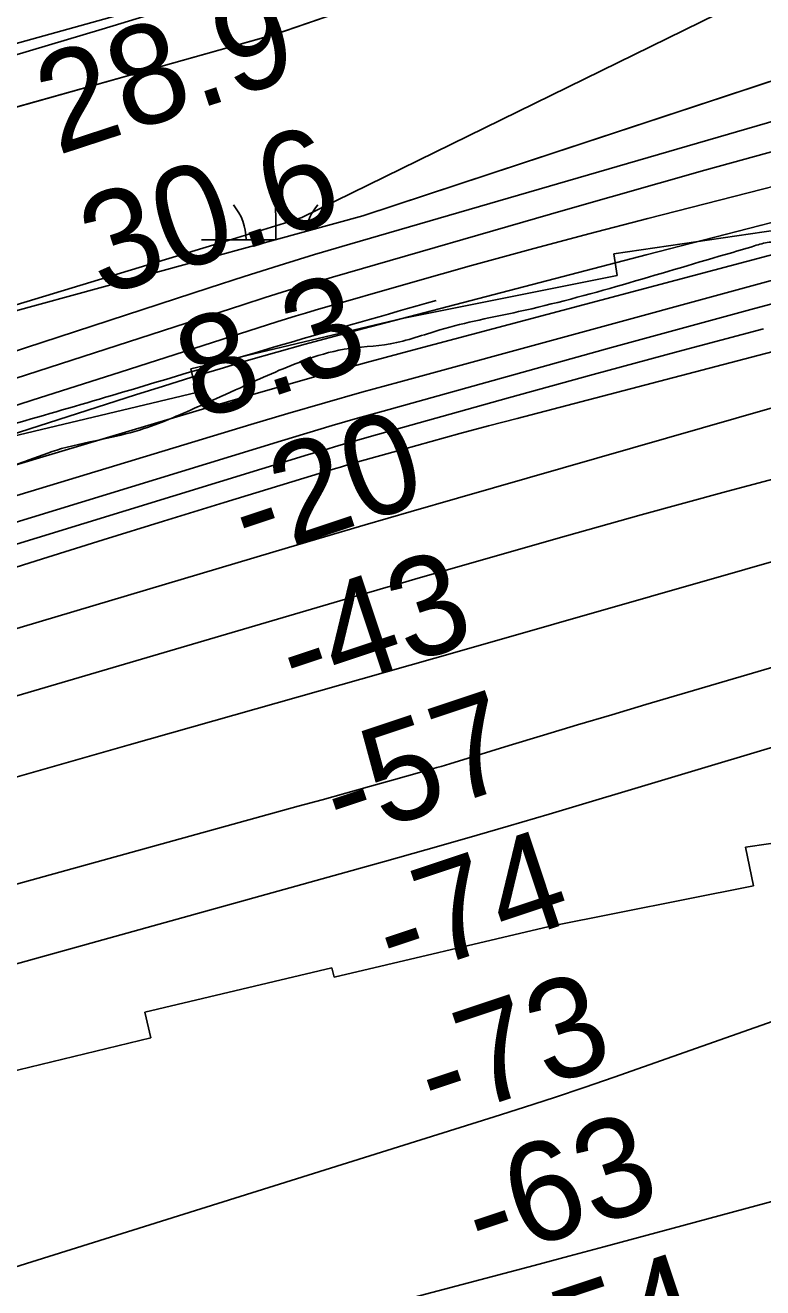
# Model space of a CAD drawing. Extents: x 3297753 to 3335611, y 652252 to 677623.
# Drawn here: x 3319873 to 3320371, y 661649 to 662501 of the extents above; entities that cross this region are included whole.
import ezdxf

# ---------------------------------------------------------------- set-up
doc = ezdxf.new("R2010")
doc.units = 0
for name, color, linetype in [('V-LEVE-TOET', 7, 'Continuous'), ('V-RIVR-EDGE', 7, 'Continuous'), ('V-RIVR-RANG', 7, 'Continuous'), ('V-ROAD-CNTR', 7, 'Continuous'), ('V-RRAP-FSHR', 7, 'Continuous'), ('V-RRAP-RVMT', 7, 'Continuous'), ('V-SITE-VEGE', 7, 'Continuous'), ('V-TOPO-DPTH', 7, 'Continuous'), ('V-TOPO-MAJR', 7, 'Continuous'), ('V-TOPO-MINR', 7, 'Continuous'), ('V-TOPO-WATR', 7, 'Continuous'), ('V-WETL-SWMP', 7, 'Continuous')]:
    doc.layers.add(name, color=color, linetype=linetype)

msp = doc.modelspace()

# ---------------------------------------------------------------- linework, layer by layer
at = {"layer": 'V-LEVE-TOET'}
msp.add_lwpolyline([(3318303.29, 661898.61), (3318349.02, 661915.96), (3318416.47, 661939.66), (3318821.54, 662099.67), (3319094.83, 662210.73), (3319129.96, 662223.38), (3319191.2, 662248.07), (3319293.71, 662284.21), (3319389.38, 662316.49), (3319441.48, 662334.46), (3319612.36, 662385.56), (3319714.56, 662413.47), (3319826.6, 662434.88), (3320041.13, 662495.21), (3320126.4, 662524.59), (3320170.6, 662537.02), (3320215.26, 662553.61), (3320268.86, 662578.67), (3320303.13, 662598.48)], dxfattribs=at)
at = {"layer": 'V-RIVR-EDGE'}
msp.add_spline([(3326889.83, 662141.04), (3326857.5, 662143.19), (3326833.47, 662147.4), (3326810.28, 662152.43), (3326793.71, 662156.2), (3326766.36, 662161.66), (3326732.8, 662165.88), (3326707.11, 662168.02), (3326687.22, 662172.21), (3326656.14, 662173.95), (3326630.03, 662175.67), (3326605.59, 662180.7), (3326578.66, 662186.99), (3326551.74, 662192.86), (3326538.9, 662196.21), (3326518.18, 662198.74), (3326492.9, 662202.12), (3326458.09, 662203.45), (3326427.02, 662208.5), (3326397.19, 662216.04), (3326383.93, 662216.48), (3326351.61, 662221.95), (3326323.86, 662228.24), (3326289.47, 662233.71), (3326274.55, 662235.82), (3326264.61, 662236.67), (3326257.56, 662236.69), (3326248.02, 662233.4), (3326240.97, 662230.1), (3326229.36, 662230.13), (3326221.9, 662230.15), (3326199.12, 662235.18), (3326175.91, 662237.72), (3326132.42, 662248.61), (3326106.72, 662250.33), (3326076.89, 662252.06), (3326054.1, 662257.5), (3326044.99, 662259.6), (3326038.77, 662259.2), (3326026.34, 662260.06), (3326018.47, 662261.32), (3326011.01, 662264.66), (3326005.63, 662265.91), (3325995.68, 662267.18), (3325979.52, 662268.05), (3325960.87, 662270.17), (3325919.03, 662276.9), (3325880.08, 662282.39), (3325827.05, 662291.64), (3325788.93, 662296.71), (3325753.29, 662300.94), (3325716.41, 662304.76), (3325674.98, 662309.01), (3325637.68, 662310.76), (3325591.68, 662315.02), (3325562.68, 662319.65), (3325528.7, 662325.54), (3325491.43, 662335.58), (3325440.89, 662347.72), (3325399.46, 662357.36), (3325379.17, 662362.38), (3325355.55, 662364.1), (3325341.45, 662364.13), (3325329.44, 662365.4), (3325309.97, 662370.84), (3325295.06, 662374.61), (3325287.6, 662374.63), (3325278.89, 662374.23), (3325263.14, 662375.1), (3325245.32, 662375.56), (3325225.84, 662376.85), (3325202.65, 662383.13), (3325187.32, 662386.48), (3325159.97, 662386.96), (3325136.34, 662385.78), (3325109.82, 662387.91), (3325071.29, 662395.47), (3325009.15, 662408.89), (3324964.41, 662419.36), (3324947, 662420.23), (3324932.09, 662421.93), (3324899.78, 662429.47), (3324835.97, 662441.65), (3324792.06, 662448.8), (3324746.88, 662451.4), (3324701.71, 662454.83), (3324664.42, 662459.89), (3324626.73, 662469.52), (3324584.88, 662476.67), (3324541.38, 662483.41), (3324493.32, 662490.99), (3324470.95, 662496.85), (3324444.44, 662503.54), (3324407.99, 662511.51), (3324387.27, 662514.46), (3324369.86, 662514.5), (3324354.93, 662512.88), (3324347.48, 662513.32), (3324329.25, 662516.68), (3324307.28, 662517.56), (3324286.15, 662522.17), (3324253.01, 662528.89), (3324226.5, 662533.93), (3324203.7, 662535.64), (3324172.21, 662538.2), (3324120.83, 662546.62), (3324040.04, 662558.84), (3324001.09, 662563.91), (3323963.38, 662564.83), (3323919.02, 662564.11), (3323879.24, 662567.94), (3323844.02, 662571.35), (3323786.85, 662582.26), (3323746.26, 662592.73), (3323704.82, 662598.63), (3323655.51, 662603.31), (3323589.62, 662609.69), (3323524.56, 662612.75), (3323466.95, 662615.8), (3323449.13, 662617.5), (3323422.62, 662622.54), (3323372.48, 662628.88), (3323343.47, 662631.44), (3323309.9, 662633.6), (3323255.19, 662632.49), (3323188.47, 662636.8), (3323129.62, 662641.5), (3323093.16, 662644.91), (3323076.99, 662643.29), (3323059.99, 662642.92), (3323032.65, 662647.13), (3322965.93, 662651.03), (3322913.71, 662656.54), (3322869.37, 662658.72), (3322809.28, 662663.85), (3322758.72, 662666.04), (3322718.52, 662666.56), (3322657.58, 662665.05), (3322608.67, 662664.76), (3322504.65, 662668.33), (3322412.64, 662669.8), (3322310.67, 662669.64), (3322271.29, 662667.25), (3322224.86, 662665.29), (3322178.85, 662663.75), (3322141.13, 662663.43), (3322102.17, 662663.94), (3322062.8, 662664.45), (3322028.82, 662667.02), (3321980.74, 662666.72), (3321909.43, 662661.93), (3321848.91, 662659.18), (3321801.24, 662655.98), (3321760.61, 662654.01), (3321739.89, 662652.81), (3321701.32, 662645.03), (3321675.19, 662638.47), (3321659.43, 662632.29), (3321646.98, 662627.76), (3321632.89, 662626.97), (3321608.43, 662625.37), (3321558.66, 662615.13), (3321529.64, 662609.4), (3321491.9, 662604.1), (3321455.01, 662601.71), (3321437.18, 662598.44), (3321411.89, 662595.18), (3321407.72, 662587.32), (3321404.39, 662581.52), (3321401.9, 662580.29), (3321396.52, 662582.37), (3321392.38, 662582.8), (3321386.99, 662582.39), (3321382.42, 662580.75), (3321374.55, 662582.84), (3321367.1, 662585.35), (3321350.51, 662582.9), (3321340.15, 662582.51), (3321332.69, 662583.77), (3321326.48, 662583.79), (3321287.49, 662572.28), (3321233.56, 662556.25), (3321160.58, 662542.34), (3321100.46, 662533.37), (3321060.64, 662524.35), (3321023.31, 662514.08), (3320998.02, 662508.75), (3320976.45, 662503.83), (3320957.38, 662500.15), (3320944.53, 662499.76), (3320930.44, 662501.46), (3320919.25, 662501.48), (3320908.47, 662499.44), (3320874.87, 662491.65), (3320813.49, 662476.46), (3320777.82, 662466.19), (3320761.24, 662464.57), (3320740.5, 662460.06), (3320702.34, 662448.14), (3320679.1, 662437.83), (3320658.77, 662428.76), (3320641.77, 662424.66), (3320616.48, 662423.07), (3320582.89, 662414.03), (3320552.18, 662401.26), (3320478.77, 662381.13), (3320420.7, 662363.45), (3320403.69, 662358.1), (3320389.17, 662354.82), (3320375.08, 662354.86), (3320365.13, 662352.4), (3320345.63, 662346.64), (3320205.86, 662308.03), (3320152.77, 662295.72), (3320119.18, 662286.27), (3320088.08, 662282.62), (3320060.29, 662274.81), (3320017.97, 662256.68), (3319991.41, 662244.73), (3319952.83, 662229.07), (3319927.94, 662222.5), (3319897.25, 662215.53), (3319872.36, 662206.89), (3319842.49, 662196.6), (3319808.07, 662187.15), (3319774.9, 662181.84), (3319711.87, 662171.22), (3319686.58, 662168.39), (3319655.89, 662160.17), (3319588.27, 662137.96), (3319508.2, 662109.14), (3319472.94, 662096.79)], degree=3, dxfattribs=at)
at = {"layer": 'V-ROAD-CNTR'}
msp.add_lwpolyline([(3321568.73, 662977.49), (3321346.43, 662923.6), (3321117.31, 662886.81), (3320965.64, 662851.42), (3320763.17, 662805.32), (3320677.25, 662784.43), (3320385.14, 662662.08), (3320181.21, 662592.85), (3319962.17, 662515.65), (3319741.75, 662454.28), (3319300.09, 662334.9), (3318986.34, 662211.61), (3318449.18, 661989.82), (3318047.95, 661827.99), (3317754.12, 661711.39), (3317613.9, 661664.2), (3317371.32, 661555.92)], dxfattribs=at)
at = {"layer": 'V-RRAP-FSHR'}
msp.add_spline([(3320150.09, 662315.57), (3320047.66, 662286.07), (3319931.17, 662251.44), (3319796.75, 662213.62), (3319527.39, 662140.55), (3319274.19, 662042.74), (3319037.81, 661963.73), (3318810.27, 661886.82), (3318640.56, 661831.26), (3318442.36, 661771.51), (3318223.46, 661674.42), (3318125.37, 661625.89), (3317894.87, 661465.55), (3317737.05, 661336.67), (3317612.9, 661222.68), (3317433.81, 661109.89), (3317347.16, 661063.4), (3317219.78, 661006.27), (3317048.57, 660941.68), (3316920.5, 660895.56), (3316802.75, 660835.25), (3316727.52, 660743.33), (3316559.69, 660646.41), (3316447.95, 660562.27), (3316323.7, 660479.21), (3316253.56, 660449.94), (3316120.17, 660384.24), (3315999.77, 660284.17), (3315912.51, 660202.12), (3315858.05, 660160.36)], degree=3, dxfattribs=at)
at = {"layer": 'V-RRAP-RVMT'}
for p, q in [((3320270.23, 662347.13), (3320417.34, 662368.67)), ((3320272.33, 662332.39), (3320270.23, 662347.13)), ((3320127.24, 662303.39), (3320272.33, 662332.39)), ((3319984.55, 662269.52), (3320127.24, 662303.39)), ((3319988.25, 662253.46), (3319984.55, 662269.52)), ((3319848.71, 662220.16), (3319988.25, 662253.46)), ((3320481.71, 661964.27), (3320359.18, 661946.46)), ((3320359.18, 661946.46), (3320364.59, 661920.45)), ((3320364.59, 661920.45), (3320226.42, 661892.9)), ((3320226.42, 661892.9), (3320081.41, 661858.71)), ((3320079.83, 661865.05), (3319953.41, 661835.1)), ((3320081.41, 661858.71), (3320079.83, 661865.05)), ((3319953.41, 661835.1), (3319957.5, 661817.81)), ((3319957.5, 661817.81), (3319803.16, 661780.28))]:
    msp.add_line(p, q, dxfattribs=at)
at = {"layer": 'V-SITE-VEGE'}
for points in [[(3318416.47, 661939.66), (3318821.54, 662099.67), (3319094.83, 662210.73), (3319129.96, 662223.38), (3319191.2, 662248.07), (3319293.71, 662284.21), (3319389.38, 662316.49), (3319441.48, 662334.46), (3319612.36, 662385.56), (3319714.56, 662413.47), (3319826.6, 662434.88), (3320041.13, 662495.21), (3320126.4, 662524.59), (3320170.61, 662537.02), (3320215.26, 662553.61), (3320268.86, 662578.67), (3320303.13, 662598.48), (3320334.28, 662613.58), (3320416.12, 662637.74)], [(3320452.03, 662488.58), (3320100.64, 662372.73), (3319863.79, 662307.91), (3319706.81, 662261.08), (3319376.1, 662153.18), (3318991.67, 662033.85), (3318581.09, 661913.52), (3318405.61, 661855.22), (3318294.33, 661822.62), (3318207.47, 661795.57), (3318164.91, 661777.16), (3318123.71, 661747.93), (3317928.72, 661578.78), (3317683.93, 661358.87), (3317490.56, 661217.34)]]:
    msp.add_lwpolyline(points, dxfattribs=at)
at = {"layer": 'V-TOPO-DPTH'}
for points in [[(3319213.6, 662032.85), (3319699.44, 662190.7), (3319758.75, 662209.92), (3319818.07, 662229.09), (3319877.42, 662248.18), (3319936.78, 662267.22), (3320042.64, 662301.09), (3320049.1, 662303.13), (3320055.56, 662305.12), (3320062.04, 662307.06), (3320068.54, 662308.96), (3320134.48, 662327.94), (3320174.01, 662339.12), (3320213.6, 662350.06), (3320253.28, 662360.65), (3320293.03, 662371), (3320784.06, 662496.55)], [(3320683.57, 662427.72), (3320137.51, 662283.02), (3320103.24, 662273.77), (3320069.03, 662264.32), (3320034.91, 662254.56), (3320000.84, 662244.59), (3319882.25, 662209.32), (3319789.03, 662181.26), (3319695.93, 662152.81), (3319603.01, 662123.76), (3319510.22, 662094.31), (3319212.72, 661998.84), (3319199.17, 661994.49), (3319185.62, 661990.13), (3319172.07, 661985.77), (3319158.53, 661981.4), (3319074.73, 661954.35), (3319019.3, 661936.38), (3318963.9, 661918.34), (3318908.55, 661900.16), (3318853.22, 661881.9), (3318510.86, 661768.46)], [(3320683.57, 662427.72), (3320137.51, 662283.02), (3320103.24, 662273.77), (3320069.03, 662264.32), (3320034.91, 662254.56), (3320000.84, 662244.59), (3319882.25, 662209.32), (3319789.03, 662181.26), (3319695.93, 662152.81), (3319603.01, 662123.76), (3319510.22, 662094.31), (3319212.72, 661998.84), (3319199.17, 661994.49), (3319185.62, 661990.13), (3319172.07, 661985.77), (3319158.53, 661981.4), (3319074.73, 661954.35), (3319019.3, 661936.38), (3318963.9, 661918.34), (3318908.55, 661900.16), (3318853.22, 661881.9), (3318510.86, 661768.46)], [(3319266.76, 661946.07), (3319843.58, 662128.27), (3319884.42, 662141.11), (3319925.28, 662153.88), (3319966.17, 662166.53), (3320007.08, 662179.11), (3320082.16, 662202.09), (3320085.55, 662203.12), (3320088.95, 662204.13), (3320092.36, 662205.12), (3320095.77, 662206.09), (3320127.51, 662215.02), (3320146.81, 662220.39), (3320166.13, 662225.69), (3320185.47, 662230.88), (3320204.84, 662235.99), (3320818.97, 662396.45)], [(3320818.97, 662396.45), (3320204.84, 662235.99), (3320185.47, 662230.88), (3320166.13, 662225.69), (3320146.81, 662220.39), (3320127.51, 662215.02), (3320095.77, 662206.09), (3320092.36, 662205.12), (3320088.95, 662204.13), (3320085.55, 662203.12), (3320082.16, 662202.09), (3320007.08, 662179.11), (3319966.17, 662166.53), (3319925.28, 662153.88), (3319884.42, 662141.11), (3319843.58, 662128.27), (3319266.76, 661946.07)], [(3318635.17, 661704.34), (3318697.54, 661726.26), (3318760.06, 661747.75), (3318822.79, 661768.58), (3318885.68, 661788.99), (3319193.24, 661887), (3319206.49, 661891.21), (3319219.74, 661895.4), (3319233, 661899.57), (3319246.27, 661903.72), (3319435.94, 661962.87), (3319544.1, 661996.37), (3319652.36, 662029.59), (3319760.75, 662062.37), (3319869.22, 662094.87), (3320039.89, 662145.64), (3320071.04, 662154.86), (3320102.21, 662164.01), (3320133.41, 662173.08), (3320164.62, 662182.08), (3320847.64, 662378.05)], [(3320847.64, 662378.05), (3320164.62, 662182.08), (3320133.41, 662173.08), (3320102.21, 662164.01), (3320071.04, 662154.86), (3320039.89, 662145.64), (3319869.22, 662094.87), (3319760.75, 662062.37), (3319652.36, 662029.59), (3319544.1, 661996.37), (3319435.94, 661962.87), (3319246.27, 661903.72), (3319233, 661899.57), (3319219.74, 661895.4), (3319206.49, 661891.21), (3319193.24, 661887), (3318885.68, 661788.99), (3318822.79, 661768.58), (3318760.06, 661747.75), (3318697.54, 661726.26), (3318635.17, 661704.34)], [(3320456.87, 662334.76), (3320362.68, 662309.57), (3320268.63, 662283.84), (3320114.36, 662240.9), (3320097.18, 662236.05), (3320080.03, 662231.11), (3320062.91, 662226.03), (3320045.82, 662220.87), (3319296.96, 661991.39)], [(3319296.96, 661991.39), (3320045.82, 662220.87), (3320062.91, 662226.03), (3320080.03, 662231.11), (3320097.18, 662236.05), (3320114.36, 662240.9), (3320268.63, 662283.84), (3320362.68, 662309.57), (3320456.87, 662334.76)], [(3319472.63, 661932.65), (3319532.76, 661950.46), (3319592.91, 661968.18), (3320096.64, 662116.07), (3320106.41, 662118.93), (3320116.18, 662121.77), (3320125.96, 662124.59), (3320135.74, 662127.39), (3320231.09, 662154.59), (3320288.61, 662170.75), (3320346.22, 662186.6), (3320403.96, 662201.97)], [(3320403.96, 662201.97), (3320346.22, 662186.6), (3320288.61, 662170.75), (3320231.09, 662154.59), (3320135.74, 662127.39), (3320125.96, 662124.59), (3320116.18, 662121.77), (3320106.41, 662118.93), (3320096.64, 662116.07), (3319592.91, 661968.18), (3319532.76, 661950.46), (3319472.63, 661932.65)]]:
    msp.add_lwpolyline(points, dxfattribs=at)
at = {"layer": 'V-TOPO-MAJR'}
for points in [[(3320732.96, 662701.72), (3320059.42, 662371.61), (3320047.75, 662367.85), (3320036.05, 662364.14), (3320024.34, 662360.5), (3320012.61, 662356.91), (3319866.51, 662312.61), (3319781.67, 662287.07), (3319696.75, 662261.78), (3319611.74, 662236.83), (3319526.65, 662212.13), (3319193.93, 662116.27), (3319171.15, 662109.71), (3319148.37, 662103.14), (3319125.6, 662096.58), (3319102.82, 662090.01), (3318753.48, 661989.24), (3318700.31, 661973.62), (3318647.24, 661957.68)], [(3318576.47, 661588.05), (3318714.96, 661638.53), (3318802.96, 661669.86), (3318891.25, 661700.3), (3318979.99, 661729.42), (3319069.03, 661757.65), (3319208.75, 661800.81), (3319228.16, 661806.76), (3319247.59, 661812.67), (3319267.04, 661818.5), (3319286.51, 661824.28), (3319564.12, 661906.13), (3319658.71, 661933.86), (3319753.35, 661961.38), (3319848.09, 661988.59), (3319942.88, 662015.6), (3320099.24, 662059.88), (3320115.9, 662064.61), (3320132.56, 662069.34), (3320149.21, 662074.09), (3320165.87, 662078.84), (3320871.39, 662280.57)]]:
    msp.add_lwpolyline(points, dxfattribs=at)
at = {"layer": 'V-TOPO-MINR'}
for points in [[(3320698.7, 662748.68), (3320046.08, 662536.48), (3320015.8, 662526.76), (3319985.46, 662517.18), (3319955.06, 662507.84), (3319924.62, 662498.64), (3319192.96, 662280.64), (3319176.85, 662275.96), (3319160.71, 662271.42), (3319144.5, 662267.1), (3319128.26, 662262.92), (3319111.97, 662258.91), (3318472.72, 661974.53), (3318444.01, 661964.55), (3318415.06, 661955.36), (3318385.77, 661947.34), (3318356.24, 661940.11), (3318325.52, 661933.25)], [(3320784.06, 662496.55), (3320293.03, 662371), (3320253.28, 662360.65), (3320213.6, 662350.06), (3320174.01, 662339.12), (3320134.48, 662327.94), (3320068.54, 662308.96), (3320062.04, 662307.06), (3320055.56, 662305.12), (3320049.1, 662303.13), (3320042.64, 662301.09), (3319936.78, 662267.22), (3319877.42, 662248.18), (3319818.07, 662229.09), (3319758.75, 662209.92), (3319699.44, 662190.7), (3319213.6, 662032.85)], [(3320568.35, 662492.05), (3320091.97, 662353.56), (3320068.1, 662346.49), (3320044.27, 662339.27), (3320020.51, 662331.81), (3319996.8, 662324.19), (3319309.07, 662099.41), (3319285.19, 662091.58), (3319261.32, 662083.73), (3319237.47, 662075.84), (3319213.62, 662067.92), (3319172.23, 662054.14), (3319169.08, 662053.09), (3319165.94, 662052.05), (3319162.79, 662051.01), (3319159.64, 662049.98), (3318463.97, 661822.31)], [(3320425.8, 662429.49), (3320331.62, 662403.43), (3320237.61, 662376.74), (3320080.26, 662331.24), (3320065.07, 662326.77), (3320049.91, 662322.2), (3320034.8, 662317.49), (3320019.71, 662312.69), (3319703.68, 662210.43), (3319614.83, 662181.61), (3319526, 662152.7), (3319437.21, 662123.67), (3319348.46, 662094.54), (3319193.1, 662043.45), (3319182.04, 662039.81), (3319170.98, 662036.19), (3319159.91, 662032.57), (3319148.84, 662028.96), (3318647.23, 661865.57)], [(3320818.97, 662396.45), (3320204.84, 662235.99), (3320185.47, 662230.88), (3320166.13, 662225.69), (3320146.81, 662220.39), (3320127.51, 662215.02), (3320095.77, 662206.09), (3320092.36, 662205.12), (3320088.95, 662204.13), (3320085.55, 662203.12), (3320082.16, 662202.09), (3320007.08, 662179.11), (3319966.17, 662166.53), (3319925.28, 662153.88), (3319884.42, 662141.11), (3319843.58, 662128.27), (3319266.76, 661946.07)], [(3320445.76, 662385.97), (3320368.92, 662366.2), (3320292.11, 662346.33), (3320215.32, 662326.39), (3320100.38, 662296.46), (3320081.09, 662291.34), (3320061.83, 662286.11), (3320042.62, 662280.71), (3320023.44, 662275.18), (3320004.31, 662269.5), (3319985.21, 662263.72), (3319966.16, 662257.78), (3319947.13, 662251.75), (3319223.03, 662018.88), (3319201.92, 662012.08), (3319180.8, 662005.28), (3319159.7, 661998.47), (3319138.59, 661991.65), (3319008.78, 661949.66), (3318922.82, 661921.69), (3318836.93, 661893.52), (3318751.14, 661865.04), (3318665.41, 661836.36), (3318520.35, 661787.55)], [(3320847.64, 662378.05), (3320164.62, 662182.08), (3320133.41, 662173.08), (3320102.21, 662164.01), (3320071.04, 662154.86), (3320039.89, 662145.64), (3319869.22, 662094.87), (3319760.75, 662062.37), (3319652.36, 662029.59), (3319544.1, 661996.37), (3319435.94, 661962.87), (3319246.27, 661903.72), (3319233, 661899.57), (3319219.74, 661895.4), (3319206.49, 661891.21), (3319193.24, 661887), (3318885.68, 661788.99), (3318822.79, 661768.58), (3318760.06, 661747.75), (3318697.54, 661726.26), (3318635.17, 661704.34)], [(3320478.78, 662357.03), (3320125.02, 662260.5), (3320099.96, 662253.55), (3320074.94, 662246.46), (3320049.98, 662239.17), (3320025.07, 662231.73), (3319524.86, 662080.16), (3319468.99, 662063.08), (3319413.16, 662045.83), (3319357.42, 662028.32), (3319301.73, 662010.63), (3319202.4, 661978.82), (3319196.42, 661976.91), (3319190.44, 661974.99), (3319184.46, 661973.06), (3319178.48, 661971.14), (3319141.25, 661959.15), (3319116.67, 661951.21), (3319092.09, 661943.25), (3319067.52, 661935.26), (3319042.95, 661927.26), (3318501.84, 661750.53)], [(3320456.87, 662334.76), (3320362.68, 662309.57), (3320268.63, 662283.84), (3320114.36, 662240.9), (3320097.18, 662236.05), (3320080.03, 662231.11), (3320062.91, 662226.03), (3320045.82, 662220.87), (3319296.96, 661991.39)], [(3320371.18, 662296.31), (3320313.68, 662281.16), (3320256.29, 662265.61), (3320198.98, 662249.79), (3320105.06, 662223.52), (3320094.77, 662220.59), (3320084.49, 662217.62), (3320074.23, 662214.58), (3320063.99, 662211.48), (3319788.91, 662127.24), (3319690.88, 662097.08), (3319592.91, 662066.74), (3319495.02, 662036.13), (3319397.18, 662005.35), (3319267.63, 661964.4), (3319234.61, 661953.95), (3319201.6, 661943.5), (3319168.59, 661933.03), (3319135.59, 661922.55), (3319102.65, 661911.89), (3319069.78, 661901), (3319037.04, 661889.76), (3319004.37, 661878.29), (3318564.62, 661721.24)], [(3319322.84, 661771.1), (3320057.04, 661974.1), (3320073.12, 661978.55), (3320089.21, 661983.02), (3320105.28, 661987.5), (3320121.36, 661991.99), (3320147.66, 661999.35), (3320150.58, 662000.18), (3320153.5, 662001.02), (3320156.41, 662001.89), (3320159.31, 662002.76), (3320199.56, 662015.08), (3320222.6, 662022.08), (3320245.65, 662029.03), (3320268.73, 662035.91), (3320291.82, 662042.73), (3320861.14, 662209.91)], [(3320403.96, 662201.97), (3320346.22, 662186.6), (3320288.61, 662170.75), (3320231.09, 662154.59), (3320135.74, 662127.39), (3320125.96, 662124.59), (3320116.18, 662121.77), (3320106.41, 662118.93), (3320096.64, 662116.07), (3319592.91, 661968.18), (3319532.76, 661950.46), (3319472.63, 661932.65)], [(3320632.82, 662090.54), (3320226.45, 661968.87), (3320198.72, 661960.66), (3320170.96, 661952.56), (3320143.16, 661944.63), (3320115.32, 661936.8), (3319712.88, 661824.96), (3319641.83, 661804.89), (3319570.9, 661784.43), (3319500.15, 661763.36), (3319429.51, 661741.89), (3319306.66, 661703.99), (3319297.58, 661701.05), (3319288.56, 661697.95), (3319279.62, 661694.61), (3319270.75, 661691.1), (3319123.99, 661630.8)], [(3319655.8, 661597.22), (3320189.45, 661764.45), (3320209.74, 661770.92), (3320229.99, 661777.53), (3320250.17, 661784.36), (3320270.3, 661791.32), (3320444.94, 661852.7)], [(3320636.94, 661777.52), (3320310.28, 661689.24), (3320286.82, 661682.93), (3320263.35, 661676.64), (3320239.87, 661670.4), (3320216.39, 661664.19), (3320042.27, 661618.29)]]:
    msp.add_lwpolyline(points, dxfattribs=at)
at = {"layer": 'V-TOPO-WATR'}
msp.add_lwpolyline([(3320683.57, 662427.72), (3320137.51, 662283.02), (3320103.24, 662273.77), (3320069.03, 662264.32), (3320034.91, 662254.56), (3320000.84, 662244.59), (3319882.25, 662209.32), (3319789.03, 662181.26), (3319695.93, 662152.81), (3319603.01, 662123.76), (3319510.22, 662094.31), (3319212.72, 661998.84), (3319199.17, 661994.49), (3319185.62, 661990.13), (3319172.07, 661985.77), (3319158.53, 661981.4), (3319074.73, 661954.35), (3319019.3, 661936.38), (3318963.9, 661918.34), (3318908.55, 661900.16), (3318853.22, 661881.9), (3318510.86, 661768.46)], dxfattribs=at)
at = {"layer": 'V-WETL-SWMP'}
for p, q in [((3320041.22, 662495.21), (3320126.48, 662524.6)), ((3319826.69, 662434.88), (3320041.22, 662495.21)), ((3320452.03, 662488.58), (3320100.64, 662372.73)), ((3320041.82, 662356.63), (3320041.78, 662392.56)), ((3320100.64, 662372.73), (3319863.79, 662307.9)), ((3319991.82, 662356.51), (3320041.57, 662356.56))]:
    msp.add_line(p, q, dxfattribs=at)
for centre, start, end in [((3319986.57, 662356.98), 359.28648, 40.83014), ((3320097.06, 662357.09), 139.28648, 171.66111)]:
    msp.add_arc(centre, 35.25, start, end, dxfattribs=at)

# ---------------------------------------------------------------- texts
at = {"layer": 'V-RIVR-RANG'}
for s, rotation, p in [('28.9', 18.14833, (3319894.39, 662413.37)), ('30.6', 18.14833, (3319924.28, 662317.94)), ('8.3', 18.14833, (3319989, 662233.92)), ('-20', 18.43569, (3320023.69, 662139.62)), ('-43', 18.43569, (3320055.83, 662044.92)), ('-57', 18.43569, (3320085.72, 661949.48)), ('-74', 18.43569, (3320121.36, 661855.95)), ('-73', 18.43569, (3320149.5, 661759.92)), ('-63', 18.43569, (3320181.39, 661665.14)), ('-54', 18.43569, (3320214.03, 661570.61))]:
    msp.add_text(s, height=67, rotation=rotation, dxfattribs=at).set_placement(p)

doc.saveas('drawing.dxf')
